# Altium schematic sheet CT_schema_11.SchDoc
size 278 x 170 mm
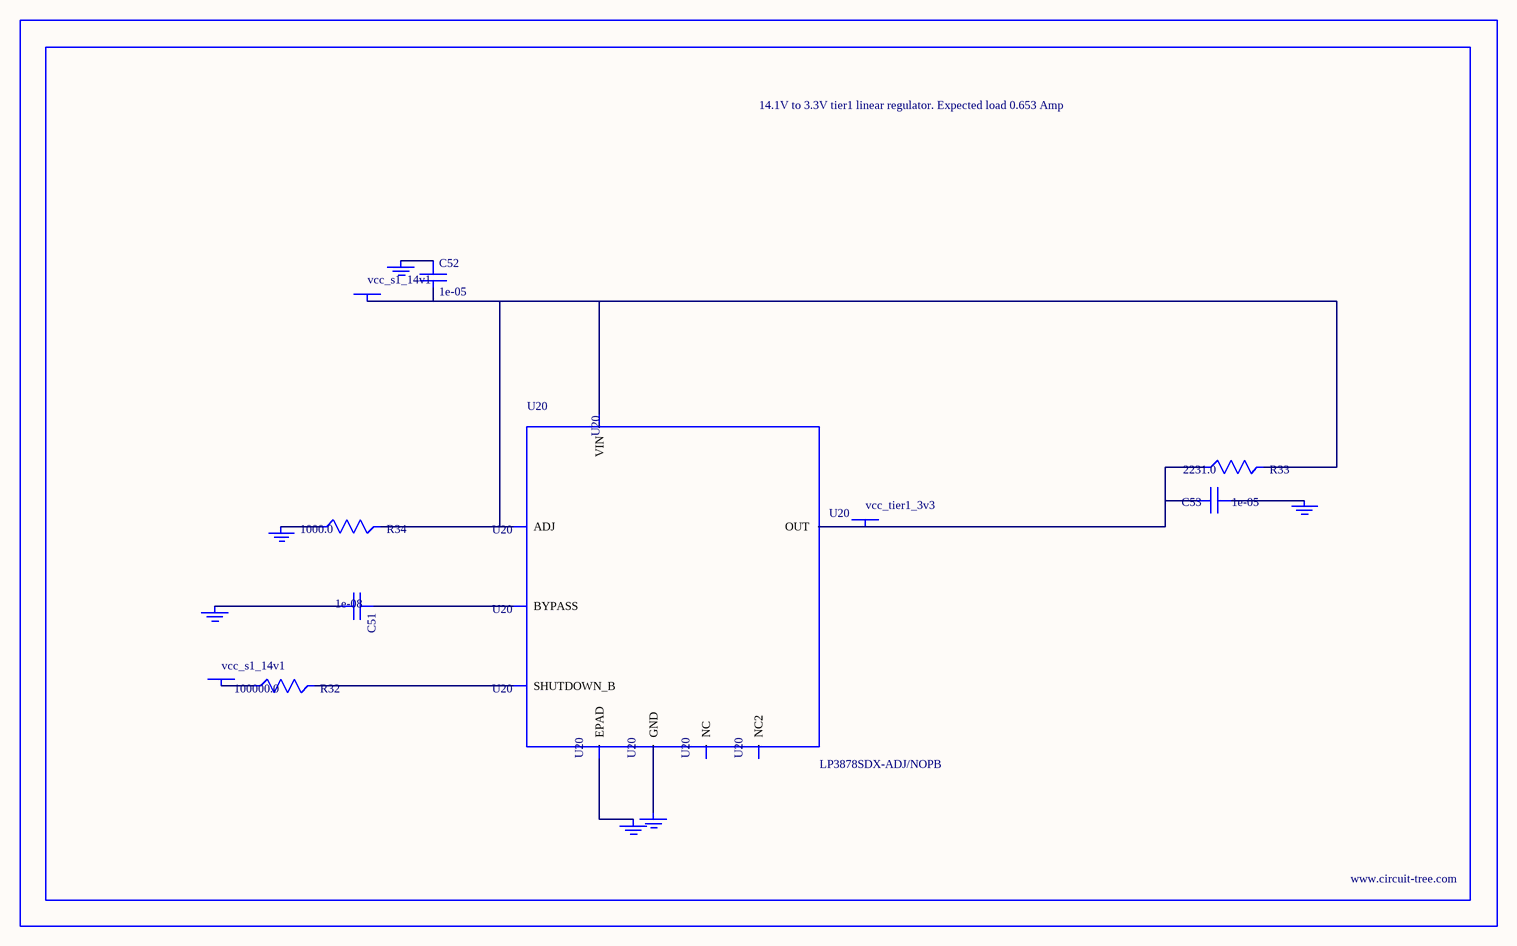
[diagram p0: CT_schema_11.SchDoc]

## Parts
BORDER10  (no value)
C51  1e-08  [C0402]
C52  1e-05  [C1210]
C53  1e-05  [C1210]
GND_INSTANCE_10_0  (no value)
GND_INSTANCE_10_1  (no value)
GND_INSTANCE_10_2  (no value)
GND_INSTANCE_10_3  (no value)
GND_INSTANCE_10_4  (no value)
GND_INSTANCE_10_5  (no value)
POWER_INSTANCE_10_0  vcc_s1_14v1
POWER_INSTANCE_10_1  vcc_s1_14v1
POWER_INSTANCE_10_2  vcc_tier1_3v3
R32  100000.0  [R0603]
R33  2231.0  [R0603]
R34  1000.0  [R0603]
U20  LP3878SDX-ADJ/NOPB  [WSON-8]

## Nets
NetC51_1: C51.1 U20.1(BYPASS)
NetC51_2: C51.2 GND_INSTANCE_10_0.0(GND)
NetC52_1: C52.1 GND_INSTANCE_10_1.0(GND)
NetC52_2: C52.2 POWER_INSTANCE_10_0.0(PWR) R33.2 R34.2 U20.4(VIN) U20.6(ADJ)
NetC53_1: C53.1 GND_INSTANCE_10_2.0(GND)
NetC53_2: C53.2 POWER_INSTANCE_10_2.0(PWR) R33.1 U20.5(OUT)
NetGND_INSTANCE_10_3_0: GND_INSTANCE_10_3.0(GND) R34.1
NetGND_INSTANCE_10_4_0: GND_INSTANCE_10_4.0(GND) U20.PAD(EPAD)
NetGND_INSTANCE_10_5_0: GND_INSTANCE_10_5.0(GND) U20.3(GND)
NetPOWER_INSTANCE_10_1_0: POWER_INSTANCE_10_1.0(PWR) R32.1
NetR32_2: R32.2 U20.8(SHUTDOWN_B)

Not connected (* = marked no-connect by the designer): U20 2(NC) 7(NC2)

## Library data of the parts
BORDER10 = BORDER_PAGE10
C51 = C0402C103K3RAC
C52 = C1210C106K5PACTU
C53 = GRM32DR61E106MA12L
GND_INSTANCE_10_0-GND_INSTANCE_10_5 = GND
POWER_INSTANCE_10_0-POWER_INSTANCE_10_2 = PWR
R32 = RC0603JR-07100KL
R33 = R33
R34 = RC0603JR-071KL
